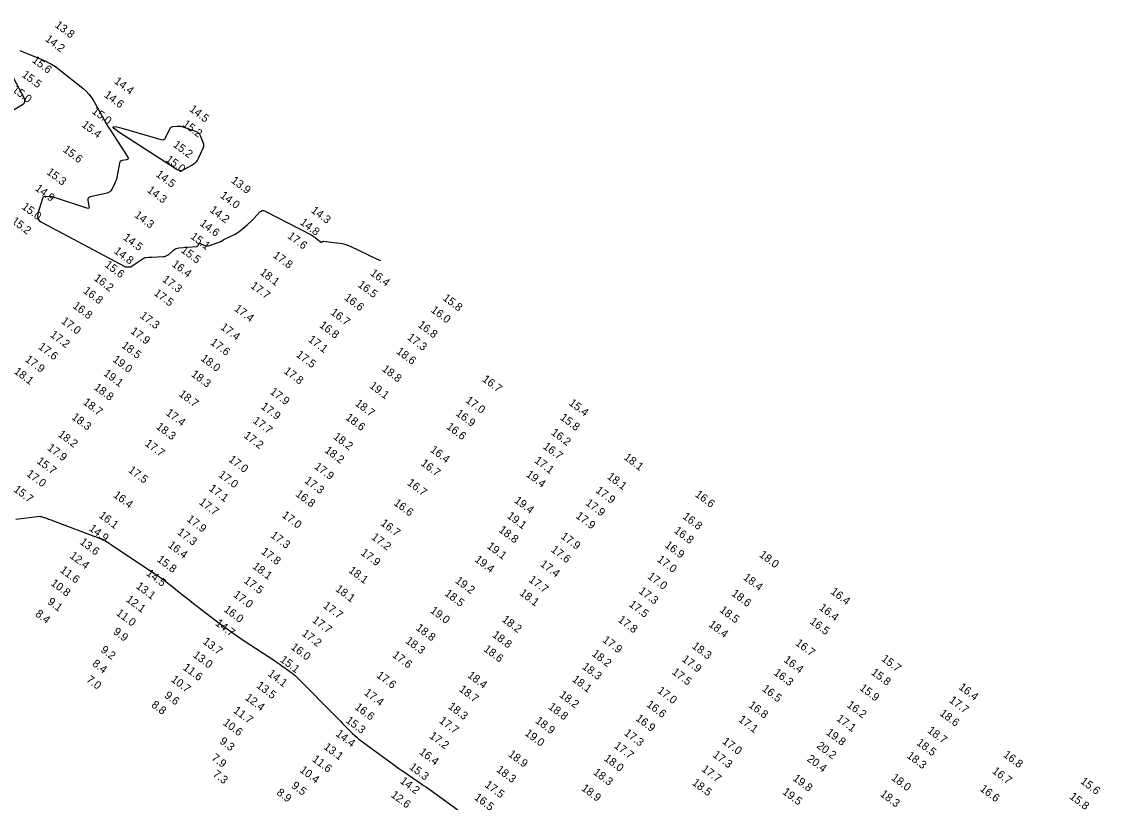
# Model space of a CAD drawing. Extents: x 988130 to 1132882, y 654656 to 841453.
# Drawn here: x 1034211 to 1034886, y 785769 to 786257 of the extents above; entities that cross this region are included whole.
import ezdxf

# ---------------------------------------------------------------- set-up
doc = ezdxf.new("R2010")
doc.units = 0
doc.layers.add('V-TOPO-MAJR', color=7, linetype='Continuous')
doc.layers.add('V-TOPO-SOUN', color=7, linetype='Continuous')

msp = doc.modelspace()

# ---------------------------------------------------------------- linework, layer by layer
at = {"layer": 'V-TOPO-MAJR'}
for points in [[(1034210.24, 786239.05), (1034224.96, 786233.02), (1034227.57, 786231.84), (1034230.08, 786230.49), (1034232.48, 786228.97), (1034234.78, 786227.27), (1034249.6, 786215.5), (1034251.6, 786213.74), (1034253.41, 786211.81), (1034255.01, 786209.71), (1034256.41, 786207.44), (1034261.6, 786198.01), (1034262.92, 786195.66), (1034264.28, 786193.34), (1034265.67, 786191.03), (1034267.1, 786188.76), (1034277.63, 786172.31), (1034277.89, 786171.75), (1034277.86, 786171.32), (1034277.56, 786171.01), (1034276.99, 786170.81), (1034274.13, 786170.28), (1034273.49, 786170.07), (1034272.99, 786169.72), (1034272.64, 786169.23), (1034272.44, 786168.58), (1034270.77, 786159.6), (1034270.55, 786158.61), (1034270.26, 786157.65), (1034269.9, 786156.71), (1034269.48, 786155.8), (1034267.63, 786152.19), (1034267.11, 786151.37), (1034266.45, 786150.72), (1034265.66, 786150.25), (1034264.73, 786149.94), (1034254.14, 786147.57), (1034253.37, 786147.28), (1034252.87, 786146.81), (1034252.65, 786146.17), (1034252.69, 786145.35), (1034253.43, 786141.71), (1034253.48, 786140.95), (1034253.26, 786140.49), (1034252.78, 786140.34), (1034252.04, 786140.48), (1034231.82, 786147.18), (1034231.14, 786147.38), (1034230.46, 786147.54), (1034229.76, 786147.64), (1034229.06, 786147.71), (1034226.22, 786147.86), (1034225.57, 786147.8), (1034225.05, 786147.57), (1034224.65, 786147.16), (1034224.38, 786146.57), (1034221.46, 786137.17), (1034221.18, 786135.49), (1034221.46, 786134.04), (1034222.29, 786132.81), (1034223.67, 786131.82), (1034275.77, 786104.14), (1034276.14, 786103.98), (1034276.52, 786103.86), (1034276.92, 786103.81), (1034277.32, 786103.8), (1034279.6, 786103.93), (1034279.69, 786103.95), (1034279.78, 786103.98), (1034279.86, 786104.02), (1034279.93, 786104.08), (1034280.22, 786104.34), (1034280.29, 786104.41), (1034280.37, 786104.47), (1034280.45, 786104.53), (1034280.53, 786104.58), (1034287.32, 786109.17), (1034287.71, 786109.4), (1034288.11, 786109.57), (1034288.54, 786109.69), (1034288.98, 786109.76), (1034290.8, 786109.9), (1034291.25, 786109.94), (1034291.71, 786109.96), (1034292.16, 786109.99), (1034292.62, 786110.01), (1034299.79, 786110.3), (1034300.75, 786110.42), (1034301.64, 786110.69), (1034302.48, 786111.11), (1034303.25, 786111.68), (1034306.23, 786114.27), (1034307, 786114.85), (1034307.84, 786115.29), (1034308.73, 786115.58), (1034309.69, 786115.73), (1034320.85, 786116.65), (1034321.11, 786116.7), (1034321.33, 786116.81), (1034321.51, 786116.97), (1034321.65, 786117.19), (1034322.15, 786118.17), (1034322.29, 786118.37), (1034322.46, 786118.48), (1034322.67, 786118.5), (1034322.9, 786118.44), (1034325.81, 786117.16), (1034326.38, 786116.97), (1034326.96, 786116.89), (1034327.54, 786116.92), (1034328.13, 786117.06), (1034335.51, 786119.57), (1034335.71, 786119.64), (1034335.9, 786119.73), (1034336.09, 786119.84), (1034336.28, 786119.96), (1034336.99, 786120.46), (1034337.17, 786120.59), (1034337.35, 786120.7), (1034337.54, 786120.81), (1034337.74, 786120.91), (1034344.74, 786124.38), (1034345.66, 786124.87), (1034346.55, 786125.42), (1034347.4, 786126.02), (1034348.22, 786126.68), (1034352.24, 786130.11), (1034352.63, 786130.44), (1034353.01, 786130.78), (1034353.4, 786131.13), (1034353.77, 786131.47), (1034355.27, 786132.87), (1034355.65, 786133.23), (1034356.01, 786133.59), (1034356.37, 786133.95), (1034356.72, 786134.33), (1034360.25, 786138.15), (1034360.98, 786138.75), (1034361.77, 786139.05), (1034362.61, 786139.04), (1034363.51, 786138.72), (1034392.28, 786123.93), (1034392.96, 786123.56), (1034393.62, 786123.15), (1034394.25, 786122.71), (1034394.87, 786122.23), (1034398.2, 786119.47), (1034398.34, 786119.38), (1034398.48, 786119.34), (1034398.63, 786119.35), (1034398.78, 786119.4), (1034399.4, 786119.71), (1034399.55, 786119.78), (1034399.71, 786119.82), (1034399.88, 786119.84), (1034400.05, 786119.83), (1034410.02, 786118.67), (1034411.72, 786118.41), (1034413.38, 786118), (1034415.01, 786117.46), (1034416.59, 786116.78), (1034433.03, 786108.91), (1034435.53, 786107.82)], [(1034205.17, 786201.44), (1034211.97, 786205.41), (1034212.92, 786206.15), (1034213.41, 786207.03), (1034213.45, 786208.03), (1034213.05, 786209.16), (1034206.35, 786221.89)], [(1034207.7, 785946.15), (1034221.01, 785947.96), (1034221.83, 785948.03), (1034222.65, 785948), (1034223.46, 785947.87), (1034224.26, 785947.65), (1034227.43, 785946.58), (1034228.23, 785946.3), (1034229.02, 785946.02), (1034229.81, 785945.74), (1034230.59, 785945.44), (1034255.45, 785936.04), (1034255.95, 785935.86), (1034256.45, 785935.67), (1034256.96, 785935.49), (1034257.46, 785935.31), (1034259.88, 785934.46), (1034260.18, 785934.35), (1034260.48, 785934.24), (1034260.78, 785934.12), (1034261.07, 785934.01), (1034262.26, 785933.53), (1034262.56, 785933.41), (1034262.84, 785933.27), (1034263.12, 785933.11), (1034263.39, 785932.94), (1034266.01, 785931.17), (1034266.54, 785930.82), (1034267.06, 785930.47), (1034267.59, 785930.11), (1034268.12, 785929.76), (1034297.13, 785910.34), (1034298.93, 785909.11), (1034300.69, 785907.85), (1034302.43, 785906.54), (1034304.14, 785905.21), (1034310.93, 785899.78), (1034312.63, 785898.43), (1034314.34, 785897.09), (1034316.05, 785895.75), (1034317.77, 785894.42), (1034335.64, 785880.7), (1034339.11, 785878.08), (1034342.64, 785875.53), (1034346.21, 785873.04), (1034349.83, 785870.62), (1034369.29, 785857.86), (1034370.48, 785857.07), (1034371.67, 785856.28), (1034372.84, 785855.47), (1034374.02, 785854.65), (1034378.69, 785851.36), (1034379.84, 785850.51), (1034380.95, 785849.62), (1034382.01, 785848.67), (1034383.04, 785847.68), (1034408.12, 785822.46), (1034409.38, 785821.19), (1034410.64, 785819.93), (1034411.9, 785818.67), (1034413.16, 785817.41), (1034418.2, 785812.38), (1034419.48, 785811.14), (1034420.81, 785809.96), (1034422.18, 785808.83), (1034423.6, 785807.75), (1034443.81, 785792.9), (1034445.49, 785791.68), (1034447.18, 785790.48), (1034448.88, 785789.29), (1034450.6, 785788.12), (1034457.48, 785783.47), (1034459.19, 785782.3), (1034460.9, 785781.12), (1034462.59, 785779.92), (1034464.28, 785778.71), (1034491.6, 785758.91)]]:
    msp.add_lwpolyline(points, dxfattribs=at)
msp.add_lwpolyline([(1034310.15, 786191.8), (1034310.83, 786191.68), (1034311.51, 786191.49), (1034319.98, 786188.63), (1034320.95, 786188.19), (1034321.76, 786187.59), (1034322.42, 786186.83), (1034322.93, 786185.9), (1034324.65, 786181.85), (1034324.97, 786180.84), (1034325.07, 786179.83), (1034324.94, 786178.83), (1034324.6, 786177.83), (1034321.71, 786171.56), (1034321.02, 786170.32), (1034320.16, 786169.22), (1034319.14, 786168.28), (1034317.95, 786167.49), (1034312.86, 786164.64), (1034311.6, 786164.12), (1034310.35, 786163.97), (1034309.11, 786164.2), (1034307.88, 786164.81), (1034272.13, 786188.12), (1034269.23, 786190.22), (1034268.45, 786191.34), (1034269.81, 786191.48), (1034273.29, 786190.65), (1034298.27, 786183.4), (1034299.33, 786183.25), (1034300.23, 786183.44), (1034300.96, 786183.99), (1034301.54, 786184.89), (1034303.91, 786190.04), (1034304.26, 786190.62), (1034304.71, 786191.05), (1034305.26, 786191.34), (1034305.92, 786191.49), (1034308.75, 786191.8), (1034309.45, 786191.83)], close=True, dxfattribs=at)

# ---------------------------------------------------------------- texts
at = {"layer": 'V-TOPO-SOUN'}
for s, p in [('13.8 ', (1034231.74, 786254.16)), ('14.2 ', (1034225.6, 786245.46)), ('15.6 ', (1034217.48, 786232.16)), ('15.5 ', (1034211.09, 786223.08)), ('14.4 ', (1034268.78, 786219.07)), ('15.0 ', (1034204.99, 786213.79)), ('14.6 ', (1034262.5, 786210.52)), ('15.0 ', (1034254.88, 786200.31)), ('14.5 ', (1034315.78, 786201.62)), ('15.4 ', (1034248.51, 786191.88)), ('15.2 ', (1034311.53, 786192.27)), ('15.6 ', (1034236.79, 786176.26)), ('15.2 ', (1034305.59, 786179.38)), ('15.0 ', (1034301, 786170.24)), ('15.3 ', (1034226.54, 786162.24)), ('14.5 ', (1034294.83, 786160.88)), ('13.9 ', (1034341.86, 786157)), ('14.9 ', (1034219.36, 786152.12)), ('14.3 ', (1034289.41, 786151.05)), ('14.0 ', (1034335.01, 786147.62)), ('15.0 ', (1034211.03, 786140.6)), ('14.3 ', (1034281.43, 786135.4)), ('14.2 ', (1034328.52, 786138.63)), ('14.3 ', (1034391.83, 786138.37)), ('15.2 ', (1034204.57, 786131.64)), ('14.6 ', (1034322.31, 786130.23)), ('14.8 ', (1034384.9, 786130.85)), ('14.5 ', (1034274.37, 786121.37)), ('15.1 ', (1034316.46, 786122.05)), ('17.6 ', (1034377.11, 786122.32)), ('14.8 ', (1034268.62, 786112.91)), ('15.5 ', (1034310.52, 786113.44)), ('17.8 ', (1034368.04, 786110.28)), ('15.6 ', (1034262.86, 786104.37)), ('16.4 ', (1034304.84, 786104.74)), ('16.2 ', (1034256.11, 786095.94)), ('17.3 ', (1034298.93, 786095.23)), ('18.1 ', (1034359.84, 786099.57)), ('16.4 ', (1034428.77, 786099.15)), ('16.8 ', (1034249.48, 786088.09)), ('17.7 ', (1034354.02, 786091.18)), ('16.5 ', (1034421.02, 786091.92)), ('17.5 ', (1034293.6, 786086.66)), ('16.6 ', (1034412.59, 786083.8)), ('15.8 ', (1034474.12, 786083.58)), ('16.8 ', (1034242.89, 786078.71)), ('17.4 ', (1034343.84, 786076.94)), ('16.7 ', (1034403.99, 786074.62)), ('16.0 ', (1034466.72, 786076.14)), ('17.0 ', (1034235.69, 786069.16)), ('17.3 ', (1034284.88, 786072.53)), ('17.2 ', (1034228.79, 786060.69)), ('17.9 ', (1034278.97, 786062.87)), ('17.4 ', (1034335.23, 786065.39)), ('16.8 ', (1034397.04, 786066.59)), ('16.8 ', (1034458.56, 786066.81)), ('18.5 ', (1034273.4, 786053.94)), ('17.6 ', (1034328.9, 786055.86)), ('17.1 ', (1034390.01, 786057.67)), ('17.3 ', (1034451.94, 786058.98)), ('17.6 ', (1034221.36, 786053.13)), ('17.5 ', (1034382.51, 786048.22)), ('18.6 ', (1034445.09, 786050.28)), ('17.9 ', (1034213.13, 786045.26)), ('19.0 ', (1034267.86, 786045.15)), ('18.0 ', (1034322.91, 786045.85)), ('18.1 ', (1034206.21, 786037.78)), ('19.1 ', (1034262.18, 786036.44)), ('18.3 ', (1034316.94, 786036)), ('17.8 ', (1034374.77, 786037.92)), ('18.8 ', (1034436.14, 786039.28)), ('18.8 ', (1034256.14, 786027.74)), ('19.1 ', (1034428.35, 786028.74)), ('16.7 ', (1034498.81, 786032.87)), ('18.7 ', (1034309.18, 786023.6)), ('17.9 ', (1034366.1, 786025.02)), ('18.7 ', (1034249.31, 786018.47)), ('17.9 ', (1034360.52, 786015.76)), ('18.7 ', (1034419.35, 786017.7)), ('17.0 ', (1034488.35, 786019.69)), ('15.4 ', (1034552.95, 786018.03)), ('18.3 ', (1034242.22, 786009.23)), ('17.4 ', (1034301.06, 786011.83)), ('17.7 ', (1034355.42, 786006.97)), ('18.6 ', (1034413.4, 786008.9)), ('16.9 ', (1034482.26, 786011.48)), ('15.8 ', (1034547.46, 786008.89)), ('18.3 ', (1034295, 786003.21)), ('16.6 ', (1034476.4, 786003.19)), ('18.2 ', (1034233.73, 785998.42)), ('17.2 ', (1034349.78, 785997.67)), ('18.2 ', (1034405.7, 785996.94)), ('16.2 ', (1034541.85, 785999.56)), ('17.9 ', (1034227.01, 785989.97)), ('17.7 ', (1034288.01, 785992.67)), ('18.2 ', (1034400.31, 785988.47)), ('16.4 ', (1034466.25, 785988.76)), ('16.7 ', (1034536.79, 785990.86)), ('15.7 ', (1034220.4, 785981.65)), ('17.0 ', (1034340.27, 785982.73)), ('16.7 ', (1034460.41, 785980.36)), ('17.1 ', (1034531.39, 785982.07)), ('18.1 ', (1034587.33, 785984.07)), ('17.0 ', (1034213.98, 785973.73)), ('17.5 ', (1034277.62, 785976.09)), ('17.0 ', (1034333.97, 785973.14)), ('17.9 ', (1034393.85, 785978.26)), ('19.4 ', (1034526.18, 785973.45)), ('17.3 ', (1034387.74, 785969.49)), ('16.7 ', (1034451.92, 785968.08)), ('18.1 ', (1034576.87, 785971.99)), ('15.7 ', (1034205.91, 785964.01)), ('16.4 ', (1034268.25, 785960.51)), ('17.1 ', (1034327.99, 785964.55)), ('16.8 ', (1034382.15, 785961.13)), ('17.9 ', (1034569.67, 785963.42)), ('16.6 ', (1034631.82, 785960.89)), ('17.7 ', (1034321.84, 785956.06)), ('16.6 ', (1034443.5, 785955.56)), ('19.4 ', (1034518.84, 785957.15)), ('17.9 ', (1034563.32, 785955.53)), ('16.1 ', (1034259.22, 785947.77)), ('17.0 ', (1034373.64, 785947.88)), ('19.1 ', (1034514.28, 785947.45)), ('17.9 ', (1034557.23, 785947.46)), ('16.8 ', (1034624.01, 785947.08)), ('14.9 ', (1034253.02, 785939.64)), ('17.9 ', (1034314.15, 785945.44)), ('16.7 ', (1034435.27, 785942.88)), ('17.3 ', (1034308.24, 785937.28)), ('17.3 ', (1034366.48, 785935.31)), ('17.2 ', (1034429.54, 785934.23)), ('18.8 ', (1034509.15, 785938.71)), ('17.9 ', (1034547.88, 785934.7)), ('16.8 ', (1034618.67, 785938.26)), ('13.6 ', (1034247.29, 785931.15)), ('16.4 ', (1034302.37, 785929.18)), ('19.1 ', (1034501.79, 785928.52)), ('17.6 ', (1034541.75, 785926.35)), ('16.9 ', (1034612.87, 785929.23)), ('12.4 ', (1034240.98, 785922.53)), ('15.8 ', (1034295.53, 785920.25)), ('17.8 ', (1034360.62, 785925.16)), ('17.9 ', (1034422.86, 785924.4)), ('19.4 ', (1034494.09, 785920.22)), ('17.0 ', (1034608.08, 785920.27)), ('18.0 ', (1034671.93, 785923.18)), ('11.6 ', (1034234.93, 785913.6)), ('18.1 ', (1034355.21, 785915.97)), ('18.1 ', (1034415.29, 785913.44)), ('17.4 ', (1034535.02, 785917.41)), ('14.5 ', (1034288.86, 785911.62)), ('17.5 ', (1034349.83, 785906.98)), ('19.2 ', (1034481.91, 785907)), ('17.7 ', (1034527.85, 785907.57)), ('17.0 ', (1034602.11, 785909.7)), ('18.4 ', (1034661.89, 785909)), ('10.8 ', (1034229.18, 785905.4)), ('13.1 ', (1034282.39, 785903.53)), ('18.1 ', (1034407.05, 785901.81)), ('18.5 ', (1034475.29, 785899.01)), ('18.1 ', (1034522.13, 785899.31)), ('17.3 ', (1034596.55, 785900.52)), ('18.6 ', (1034654.62, 785898.96)), ('16.4 ', (1034716.5, 785900.16)), ('9.1', (1034227.17, 785893.82)), ('12.1 ', (1034276.19, 785895.31)), ('17.0 ', (1034343.23, 785898.17)), ('17.5 ', (1034590.46, 785892.2)), ('8.4', (1034219.51, 785886.2)), ('11.0 ', (1034270.02, 785886.76)), ('16.0 ', (1034337.3, 785889.03)), ('17.7 ', (1034399.35, 785891.38)), ('19.0 ', (1034466.32, 785888.36)), ('18.5 ', (1034647.15, 785888.69)), ('16.4 ', (1034709.31, 785890.09)), ('14.7 ', (1034332, 785880.43)), ('17.7 ', (1034392.55, 785882.36)), ('18.2 ', (1034511.12, 785882.74)), ('17.8 ', (1034583.57, 785882.54)), ('18.4 ', (1034640.26, 785879.66)), ('16.5 ', (1034703.53, 785881.42)), ('9.9', (1034268.2, 785875.09)), ('17.2 ', (1034386.05, 785874.01)), ('18.8 ', (1034457.33, 785877.49)), ('18.8 ', (1034505.07, 785873.13)), ('13.7 ', (1034324.16, 785868.94)), ('16.0 ', (1034379.22, 785865.48)), ('18.3 ', (1034450.8, 785869.41)), ('17.9 ', (1034573.97, 785869.97)), ('18.3 ', (1034629.85, 785866.14)), ('16.7 ', (1034694.51, 785867.99)), ('9.2', (1034260.36, 785863.73)), ('13.0 ', (1034318.02, 785860.55)), ('17.6 ', (1034442.65, 785860.54)), ('18.6 ', (1034499.65, 785864.28)), ('18.2 ', (1034567.3, 785861.33)), ('8.4', (1034255.06, 785855.13)), ('11.6 ', (1034311.75, 785852.72)), ('15.1 ', (1034372.48, 785857.61)), ('18.3 ', (1034561.2, 785853.26)), ('17.9 ', (1034623.56, 785857.95)), ('16.4 ', (1034687.22, 785857.52)), ('15.7 ', (1034748.24, 785858.21)), ('7.0', (1034251.38, 785845.1)), ('10.7 ', (1034304.31, 785845.29)), ('14.1 ', (1034364.74, 785848.82)), ('17.6 ', (1034432.69, 785847.87)), ('18.4 ', (1034489.59, 785847.89)), ('18.1 ', (1034554.97, 785845.38)), ('17.5 ', (1034617.32, 785849.9)), ('16.3 ', (1034680.95, 785849.49)), ('15.8 ', (1034741.83, 785849.7)), ('13.5 ', (1034357.72, 785841.46)), ('18.7 ', (1034484.28, 785839.16)), ('17.0 ', (1034608.25, 785838.29)), ('16.5 ', (1034673.68, 785839.41)), ('15.9 ', (1034734.64, 785839.94)), ('16.4 ', (1034796.59, 785840.43)), ('9.6', (1034300.19, 785835.3)), ('12.4 ', (1034350.57, 785833.91)), ('17.4 ', (1034424.98, 785837)), ('18.2 ', (1034546.99, 785835.65)), ('17.7 ', (1034790.59, 785832.31)), ('8.8', (1034292, 785829.34)), ('11.7 ', (1034343.25, 785825.86)), ('16.6 ', (1034419.12, 785828.03)), ('18.3 ', (1034477.51, 785828.37)), ('18.8 ', (1034540.12, 785828.17)), ('16.6 ', (1034601.45, 785829.62)), ('16.8 ', (1034665.24, 785829.2)), ('16.2 ', (1034726.67, 785829.37)), ('10.6 ', (1034336.78, 785818.19)), ('15.3 ', (1034413.51, 785819.66)), ('17.7 ', (1034471.89, 785819.54)), ('18.9 ', (1034531.94, 785819.42)), ('16.9 ', (1034594.68, 785820.92)), ('17.1 ', (1034658.93, 785820.22)), ('17.1 ', (1034720.16, 785820.8)), ('18.6 ', (1034784.68, 785824.14)), ('14.4 ', (1034407.19, 785811.31)), ('19.0 ', (1034525.42, 785811.73)), ('17.3 ', (1034587.45, 785811.79)), ('19.8 ', (1034713.73, 785812.15)), ('18.7 ', (1034777, 785813.38)), ('9.3', (1034334.67, 785806.63)), ('17.2 ', (1034465.76, 785810.03)), ('17.0 ', (1034648.82, 785806.59)), ('18.5 ', (1034770.21, 785805.72)), ('13.1 ', (1034399.69, 785803.12)), ('16.4 ', (1034459.39, 785799.94)), ('18.9 ', (1034514.99, 785798.6)), ('17.7 ', (1034581.18, 785803.86)), ('17.3 ', (1034642.85, 785798.19)), ('20.2 ', (1034707.79, 785803.84)), ('18.3 ', (1034764.13, 785797.63)), ('16.8 ', (1034824.4, 785798.26)), ('7.9', (1034329.6, 785796.24)), ('11.6 ', (1034392.55, 785795.46)), ('18.0 ', (1034574.87, 785795.93)), ('20.4 ', (1034701.76, 785795.61)), ('7.3', (1034330.47, 785786.07)), ('10.4 ', (1034384.74, 785788.65)), ('15.3 ', (1034453.16, 785790.54)), ('18.3 ', (1034507.64, 785788.94)), ('18.3 ', (1034568.17, 785787.27)), ('17.7 ', (1034635.86, 785789.26)), ('16.7 ', (1034817.48, 785788.08)), ('9.5', (1034379.64, 785778.87)), ('14.2 ', (1034447.43, 785781.85)), ('17.5 ', (1034500.38, 785779.41)), ('18.5 ', (1034629.95, 785780.71)), ('19.8 ', (1034692.92, 785783.48)), ('18.0 ', (1034754.47, 785783.84)), ('15.6 ', (1034872.63, 785781.65)), ('8.9', (1034370.28, 785774.57)), ('12.6 ', (1034441.77, 785773.14)), ('16.5 ', (1034493.83, 785771.59)), ('18.9 ', (1034560.76, 785777.31)), ('19.5 ', (1034686.41, 785775.03)), ('18.3 ', (1034747.48, 785773.71)), ('16.6 ', (1034809.81, 785776.96)), ('15.8 ', (1034865.79, 785772.1))]:
    msp.add_text(s, height=5, rotation=323, dxfattribs=at).set_placement(p)

doc.saveas('drawing.dxf')
